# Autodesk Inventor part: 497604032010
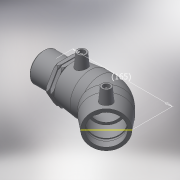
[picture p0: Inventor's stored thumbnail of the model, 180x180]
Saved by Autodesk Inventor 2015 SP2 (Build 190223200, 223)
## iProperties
Created: 2017-06
Part Number: 497604032010
Material: Generic
Description: PLASSON PE MALE TRANSITION 45° ELBOW 32-1"
Document SubType Name: Modeling
Designer: KIM
Mass: 55.0731 g
Surface Area: 148.067 cm^2
Volume: 55.0731 cm^3
Density: 1 g/cm^3
Appearance: Default
Author: KIM
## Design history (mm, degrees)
derived "497604.ipt"
feature "Solid1::497604.ipt"
tag "TaggingFeature1"
body "Solid1"
other parameters: "d2" = 44, "d4" = 25.5, "d5" = 39.6, "d8" = 168 deg, "d10" = 15.6, "d11" = 5.2, "d29" = 43, "d30" = 15, "d31" = 35.7, "d34" = 5 deg, "d41" = 4, "d42" = 14, "d43" = 0, "d49" = 32, "d50" = 27.2, "d51" = 15.6, "d52" = 38.9, "d54" = 135 deg, "d86" = 19.8, "d87" = 135 deg, "d88" = 102, "d90" = 31.2, "d91" = 0, "d92" = 39, "d93" = 0, "d101" = 3, "d102" = 0, "d107" = 0.1, "d108" = 24, "d109" = 33.249, "d110" = 39, "d111" = 9.75, "d112" = 44, "d113" = 23.2743, "d114" = 35.1, "d116" = 1.32, "d122" = 0, "d123" = 1.66245, "d126" = 0.975, "d127" = 4.3875, "d128" = 44, "d130" = 39, "d131" = 32, "d_" = 32, "L_" = 141, "L_2" = 39, "D_" = 24, "A_" = 43, "d_2" = 12, "L_1" = 39, "R_" = 33.249, "D_1" = 44, "d129" = 141
